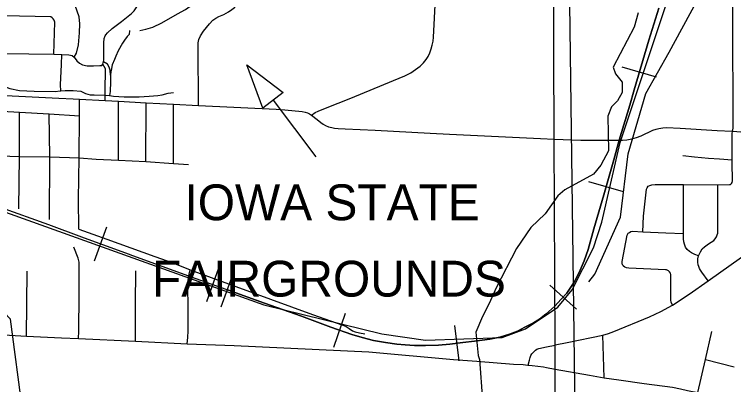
# Model space of a CAD drawing. Extents: x -1403959 to 81668, y -1400582 to 11018.
# Drawn here: x 7531.9 to 7677.6, y 8209.8 to 8284.8 of the extents above; entities that cross this region are included whole.
import ezdxf

# ---------------------------------------------------------------- set-up
doc = ezdxf.new("R2010")
doc.units = 0
for name, color, linetype in [('tdCiHydroTxt', 7, 'Continuous'), ('tdCiRRCL', 7, 'Continuous'), ('tdCiSectNmbr', 7, 'Continuous'), ('tdCiSectTwpRng', 7, 'Continuous'), ('tdCoSecRteBand', 7, 'Continuous'), ('tdCoStrucNonDivPri', 7, 'Continuous'), ('tdCoStrucSec', 7, 'Continuous'), ('tdCoSurfBitum', 7, 'Continuous'), ('tdCoTwpNameTxt', 7, 'Continuous')]:
    doc.layers.add(name, color=color, linetype=linetype)

msp = doc.modelspace()

# ---------------------------------------------------------------- linework, layer by layer
at = {"layer": 'tdCiHydroTxt'}
for points in [[(7543.99, 8276.06), (7544.47, 8276.9), (7544.82, 8278.62), (7545.03, 8281.03), (7545.09, 8282.84), (7544.99, 8284.25), (7543.79, 8287.74), (7543.55, 8288.67), (7543.47, 8290.45), (7543.41, 8293.01)], [(7550.41, 8280.6), (7550.72, 8281.01), (7551.69, 8281.91), (7553.53, 8283.33), (7555.58, 8284.91), (7556.14, 8285.47), (7556.55, 8286.06), (7557.03, 8286.89), (7557.23, 8287.69), (7557.19, 8288.74), (7557.08, 8289.79), (7556.63, 8290.51)], [(7557.27, 8281.51), (7558.46, 8281.77), (7559.88, 8282.19), (7561.71, 8283.04), (7564.93, 8284.9), (7566.52, 8285.73), (7567.44, 8286.41), (7567.79, 8286.87), (7568.18, 8287.61), (7568.25, 8288.58), (7568.19, 8290.36)], [(7569.13, 8266.32), (7569.06, 8278.31), (7569.09, 8278.99), (7569.24, 8279.66), (7569.56, 8280.38), (7570.18, 8281.37), (7571.36, 8282.86), (7572.03, 8283.57), (7572.64, 8284.02), (7573.26, 8284.34), (7574.29, 8284.75), (7575.24, 8285.25), (7575.89, 8285.73), (7576.44, 8286.14), (7577.07, 8286.79), (7577.61, 8287.4), (7577.99, 8288.06), (7578.27, 8288.8), (7578.29, 8289.24), (7578.25, 8289.86)], [(7539.71, 8283.88), (7539.53, 8284.07), (7539.24, 8284.23), (7529.69, 8284.43)], [(7539.88, 8276.7), (7540.03, 8283.21), (7539.93, 8283.6), (7539.71, 8283.88)], [(7555.17, 8281.51), (7555.09, 8280.71), (7554.72, 8280.26), (7554.14, 8279.51), (7553.75, 8278.94), (7552.9, 8277.36), (7552.41, 8276.26), (7552.11, 8275.6), (7551.64, 8274.52), (7551.45, 8273.41), (7551.42, 8273.16)], [(7549.9, 8275.12), (7549.96, 8275.54), (7549.96, 8278.96), (7550.04, 8279.88), (7550.26, 8280.42), (7550.41, 8280.6)], [(7529.71, 8276.85), (7539.88, 8276.7), (7541.47, 8276.62), (7542.89, 8276.59), (7543.57, 8276.44), (7543.99, 8276.06)], [(7541.24, 8269.26), (7541.23, 8270.47), (7541.37, 8274.61), (7541.47, 8276.62)], [(7543.99, 8276.06), (7544.54, 8275.37), (7545.08, 8274.88), (7545.67, 8274.51), (7546.57, 8274.34), (7547.91, 8274.34), (7549.16, 8274.37), (7549.6, 8274.4), (7549.81, 8274.66)], [(7549.81, 8274.66), (7549.87, 8274.93), (7549.9, 8275.12)], [(7551.36, 8272.46), (7551.23, 8273.45), (7551.06, 8274.09), (7550.72, 8274.66), (7549.9, 8275.12)], [(7550.22, 8267.28), (7550.23, 8268.38), (7550.25, 8269.82), (7550.34, 8273.15), (7550.29, 8273.72), (7549.81, 8274.66)], [(7551.42, 8273.16), (7551.36, 8272.46), (7551.32, 8271.08), (7551.23, 8269.14), (7551.11, 8268.31)], [(7529.59, 8270.08), (7529.61, 8270.08), (7530.06, 8270.1), (7530.94, 8269.73), (7532.92, 8269.31), (7535.85, 8269.21), (7540.09, 8269.12), (7541.16, 8269.25)], [(7541.16, 8269.25), (7541.24, 8269.26), (7542.16, 8269.37), (7543.75, 8269.34), (7545.34, 8269.17), (7546.26, 8268.71), (7547.21, 8268.46), (7547.99, 8268.46), (7550.19, 8268.38)], [(7550.19, 8268.38), (7550.23, 8268.38), (7551.11, 8268.31), (7551.97, 8268.17), (7554.09, 8268.07), (7557.14, 8268.05), (7559.16, 8268.17), (7560.9, 8268.31), (7561.8, 8268.46), (7563.04, 8268.78), (7564.07, 8268.93)]]:
    msp.add_lwpolyline(points, dxfattribs=at)
at = {"layer": 'tdCiRRCL'}
msp.add_lwpolyline([(7641.92, 8143.14), (7641.42, 8212.91), (7641.4, 8217.78), (7641.24, 8259.51), (7640.95, 8331.05)], dxfattribs=at)
msp.add_lwpolyline([(7641.92, 8143.14), (7641.42, 8212.91), (7641.4, 8217.78), (7641.24, 8259.51), (7640.95, 8331.05)], dxfattribs=at)
at = {"layer": 'tdCiSectNmbr'}
for points in [[(7592.05, 8264.37), (7592.8, 8264.86), (7593.41, 8265.17), (7594.89, 8265.73), (7600, 8267.8), (7608.67, 8271.38), (7610.93, 8272.3), (7612.21, 8272.94), (7613.13, 8273.58), (7614.06, 8274.29), (7614.77, 8274.95), (7615.26, 8275.63), (7615.66, 8276.22), (7616.05, 8276.95), (7616.3, 8277.78), (7616.53, 8278.54), (7616.69, 8279.32), (7616.78, 8280.14), (7618.07, 8304.79)], [(7530.05, 8268.32), (7540.86, 8267.75)], [(7540.86, 8267.75), (7543.78, 8267.62), (7545.06, 8267.55)], [(7545.06, 8267.55), (7550.22, 8267.28), (7552.94, 8267.18), (7558.55, 8266.86), (7564.11, 8266.57), (7569.13, 8266.32), (7584.89, 8265.58), (7586.65, 8265.43), (7590.14, 8265.11), (7590.78, 8264.98), (7591.27, 8264.8), (7591.63, 8264.63), (7592.05, 8264.37)], [(7592.05, 8264.37), (7593.17, 8263.46), (7593.94, 8262.84), (7594.42, 8262.52), (7594.9, 8262.26), (7595.52, 8262), (7596.15, 8261.84), (7596.73, 8261.74), (7597.44, 8261.67), (7598.84, 8261.56), (7604.97, 8261.3), (7616.11, 8260.68), (7619.98, 8260.5)], [(7619.98, 8260.5), (7638.44, 8259.64), (7641.24, 8259.51)], [(7658.82, 8260.15), (7661.21, 8261.27), (7661.85, 8261.51), (7662.42, 8261.64), (7663.2, 8261.77), (7664, 8261.83), (7666.77, 8261.7), (7674.27, 8261.25), (7677.29, 8261.1), (7677.37, 8261.1), (7677.46, 8261.09), (7683.65, 8260.56), (7689.52, 8260.18)], [(7641.24, 8259.51), (7646.62, 8259.26), (7649.6, 8259.25), (7654.07, 8259.25), (7655.07, 8259.25), (7655.96, 8259.34), (7656.93, 8259.53), (7657.88, 8259.79), (7658.82, 8260.15)], [(7668.57, 8228.07), (7672.43, 8230.76), (7689.63, 8243.01)], [(7641.42, 8217.79), (7643.83, 8218.29), (7651.07, 8219.8), (7652.25, 8220.14), (7653.33, 8220.53), (7660.52, 8223.51), (7662.81, 8224.56), (7665.19, 8225.84), (7668.57, 8228.07)], [(7525.09, 8220.11), (7525.09, 8220.11), (7534.34, 8219.54), (7541.4, 8219.23), (7544.87, 8219.11), (7556.37, 8218.54), (7566.88, 8218.01)], [(7651.34, 8211.12), (7651.07, 8219.8)], [(7566.88, 8218.01), (7576.4, 8217.66), (7603.7, 8216.4), (7620.82, 8214.84), (7625.57, 8214.48), (7632.98, 8213.93), (7634.95, 8213.81), (7635.89, 8213.72)], [(7635.92, 8213.72), (7636.21, 8214.72), (7636.37, 8215.28), (7636.51, 8215.65), (7636.71, 8215.99), (7637, 8216.36), (7637.42, 8216.73), (7637.72, 8216.91), (7638.1, 8217.06), (7639.69, 8217.42), (7641.4, 8217.78)], [(7641.4, 8217.78), (7641.42, 8217.79)], [(7635.89, 8213.72), (7635.92, 8213.72), (7636.75, 8213.64), (7637.88, 8213.51), (7639.06, 8213.34), (7639.68, 8213.23), (7641.42, 8212.91), (7641.43, 8212.91)], [(7641.43, 8212.91), (7648.39, 8211.64)], [(7648.39, 8211.64), (7651.34, 8211.12), (7654.32, 8210.7)], [(7654.32, 8210.7), (7659.47, 8209.97), (7665.18, 8209.21), (7666.83, 8208.89), (7668.23, 8208.57), (7670.31, 8208.13)]]:
    msp.add_lwpolyline(points, dxfattribs=at)
at = {"layer": 'tdCiSectTwpRng'}
for points in [[(7677.37, 8261.1), (7677.46, 8261.7), (7677.47, 8264.86), (7677.35, 8297.87)], [(7544.96, 8255.69), (7545.02, 8264.21), (7545.06, 8267.55)], [(7552.95, 8255.2), (7552.94, 8267.18)], [(7558.5, 8254.94), (7558.55, 8266.86)], [(7564.07, 8254.58), (7564.11, 8266.57)], [(7520.84, 8265.61), (7526.95, 8265.3), (7532.9, 8264.95), (7538.93, 8264.6), (7545.02, 8264.21)], [(7532.89, 8255.97), (7532.9, 8264.95)], [(7539.03, 8255.92), (7538.93, 8264.6)], [(7677.3, 8255.32), (7677.29, 8260.57), (7677.37, 8261.09)], [(7677.37, 8261.09), (7677.37, 8261.1), (7677.37, 8261.1)], [(7521.18, 8256.22), (7526.89, 8256.18), (7532.89, 8255.97), (7539.03, 8255.92), (7544.96, 8255.69), (7544.96, 8255.69)], [(7667.28, 8256.17), (7669.66, 8255.87), (7672.45, 8255.63), (7674.68, 8255.47), (7677.3, 8255.32)], [(7532.74, 8245.37), (7532.89, 8255.97)], [(7538.97, 8243.21), (7539.03, 8255.92)], [(7544.93, 8241.26), (7544.85, 8247.31), (7544.96, 8255.69)], [(7544.96, 8255.69), (7548.43, 8255.45), (7552.95, 8255.2), (7558.5, 8254.94), (7564.07, 8254.58), (7567.13, 8254.35)], [(7672.43, 8230.76), (7671.13, 8232.53), (7670.88, 8232.91), (7670.68, 8233.29), (7670.51, 8233.66), (7670.41, 8234.05), (7670.35, 8234.56), (7670.34, 8235.21), (7670.48, 8235.84), (7670.84, 8236.68), (7671.23, 8237.25), (7671.67, 8237.7), (7672.5, 8238.26), (7673.54, 8238.96), (7673.86, 8239.29), (7674.1, 8239.72), (7674.26, 8240.1), (7674.34, 8240.42), (7674.35, 8240.86), (7674.4, 8250.25), (7676.72, 8250.27), (7676.94, 8250.32), (7677.13, 8250.48), (7677.26, 8250.73), (7677.33, 8251.06), (7677.3, 8254.78), (7677.3, 8255.32)], [(7659.15, 8240.7), (7659.29, 8243.89), (7659.84, 8248.75), (7659.94, 8249.33), (7660.06, 8249.64), (7660.29, 8249.94), (7660.6, 8250.12), (7661.03, 8250.24), (7661.68, 8250.27), (7667.43, 8250.27), (7674.4, 8250.25)], [(7670.48, 8235.84), (7669.68, 8236.14), (7669.01, 8236.44), (7668.6, 8236.74), (7668.17, 8237.13), (7667.84, 8237.6), (7667.59, 8238.18), (7667.46, 8238.7), (7667.41, 8239.26), (7667.4, 8240.39), (7667.43, 8250.27)], [(7544.93, 8241.26), (7550.56, 8239.24)], [(7655.28, 8233.74), (7655.23, 8233.79), (7655.09, 8234.02), (7655, 8234.34), (7654.98, 8234.71), (7656.03, 8240.05), (7656.21, 8240.42), (7656.45, 8240.59), (7656.72, 8240.74), (7657.08, 8240.81), (7659.15, 8240.7), (7663.82, 8240.5)], [(7663.82, 8240.5), (7667.4, 8240.39)], [(7550.56, 8239.24), (7560.34, 8235.74), (7563.98, 8234.44), (7567.44, 8233.02), (7592.24, 8223.98), (7592.24, 8223.98)], [(7544.95, 8234.59), (7544.8, 8235.35), (7543.92, 8237.59)], [(7544.87, 8219.11), (7544.94, 8220.56), (7544.97, 8227.97), (7544.95, 8234.59)], [(7534.34, 8219.54), (7534.44, 8232.76)], [(7556.37, 8218.54), (7556.37, 8224.26), (7556.38, 8226.12), (7556.47, 8232.8)], [(7566.88, 8218.01), (7566.98, 8219.33), (7567.07, 8220.62), (7567.05, 8225.11), (7567.03, 8229.94), (7567.15, 8231.47), (7567.28, 8232.13), (7567.44, 8233.02)], [(7665.19, 8225.84), (7664.95, 8226.45), (7664.87, 8226.88), (7664.82, 8232.06), (7664.76, 8232.36), (7664.59, 8232.61), (7664.36, 8232.82), (7663.99, 8232.99), (7663.75, 8233.04), (7656.32, 8233.32), (7655.85, 8233.38), (7655.52, 8233.52), (7655.28, 8233.74)], [(7592.24, 8223.98), (7598.41, 8221.82), (7599.07, 8221.54), (7599.65, 8221.09), (7600.36, 8220.67), (7600.89, 8220.48), (7601.8, 8220.27), (7602.89, 8220.05)], [(7670.31, 8208.13), (7671.85, 8214.83), (7673.16, 8220.51)], [(7671.85, 8214.83), (7677.67, 8213.39)]]:
    msp.add_lwpolyline(points, dxfattribs=at)
at = {"layer": 'tdCoSecRteBand'}
for p, q in [((7661.96, 8272.03), (7655, 8274.07)), ((7655.25, 8248.83), (7648.27, 8250.81)), ((7548.12, 8234.86), (7550.57, 8241.69)), ((7570.84, 8226.6), (7573.3, 8233.43)), ((7573.78, 8225.54), (7576.24, 8232.37)), ((7645.74, 8225.06), (7640.33, 8229.9)), ((7596.58, 8217.35), (7598.95, 8224.21)), ((7621.99, 8214.55), (7621.1, 8221.74))]:
    msp.add_line(p, q, dxfattribs=at)
for points in [[(7501.68, 8253), (7525.64, 8246.21), (7582.4, 8225.9), (7606.28, 8220.05), (7615.18, 8218.76), (7630.67, 8219.28), (7635.44, 8221.08), (7641.96, 8225.42), (7644.87, 8228.93), (7649.17, 8237.46), (7650.86, 8242.65), (7654.57, 8258.82), (7664.88, 8289.64), (7673.02, 8304.73), (7684.51, 8321.19)], [(7648.25, 8230.6), (7649.46, 8232.12), (7654.68, 8243.71), (7656.24, 8256.53), (7659.79, 8268.73), (7664.54, 8277.12), (7670.07, 8287.33), (7675.6, 8301.52), (7680.98, 8311.73), (7688.18, 8321.02)], [(7662.39, 8285.99), (7660.39, 8279.55), (7657.43, 8269.49), (7656.57, 8266.38), (7654.4, 8259.25), (7653.31, 8255.29), (7651.31, 8248.21), (7649.25, 8241.32), (7648.09, 8237.16), (7647.28, 8234.82), (7646.26, 8232.47), (7645.25, 8230.54), (7643.75, 8228.28), (7642.66, 8227.07), (7641.33, 8225.62), (7639.54, 8224.05), (7638.22, 8223.01), (7637.03, 8222.25), (7635.28, 8221.36), (7633.79, 8220.57), (7632.16, 8219.97), (7630.24, 8219.38), (7628.16, 8218.95), (7625.07, 8218.58), (7622.73, 8218.29), (7620.07, 8217.96), (7617.79, 8217.78), (7615.12, 8217.68), (7612.92, 8217.68), (7611.04, 8217.81), (7609.34, 8217.94), (7607.06, 8218.27), (7604.6, 8218.72), (7602.29, 8219.28), (7600.19, 8219.94), (7596, 8221.39), (7590, 8223.59), (7582.52, 8226.25), (7575.01, 8228.96)], [(7575.01, 8228.96), (7582.52, 8226.25), (7590, 8223.59), (7596, 8221.39), (7600.19, 8219.94), (7602.29, 8219.28), (7604.6, 8218.72), (7607.06, 8218.27), (7609.34, 8217.94), (7611.04, 8217.81), (7612.92, 8217.68), (7615.12, 8217.68), (7617.79, 8217.78), (7620.07, 8217.96), (7622.73, 8218.29), (7625.07, 8218.58), (7628.16, 8218.95), (7630.24, 8219.38), (7632.16, 8219.97), (7633.79, 8220.57), (7635.28, 8221.36), (7637.03, 8222.25), (7638.22, 8223.01), (7639.54, 8224.05), (7641.33, 8225.62), (7642.66, 8227.07), (7643.75, 8228.28), (7645.25, 8230.54), (7646.26, 8232.47), (7647.28, 8234.82), (7648.09, 8237.16), (7649.25, 8241.32), (7651.31, 8248.21), (7653.31, 8255.29), (7654.4, 8259.25), (7656.57, 8266.38), (7657.43, 8269.49), (7660.39, 8279.55), (7662.39, 8285.99)], [(7528.89, 8245.68), (7538.78, 8242.18), (7545.47, 8239.67), (7554.93, 8236.27), (7555.82, 8235.94), (7568.65, 8231.25), (7574.73, 8229.06), (7575.01, 8228.96)], [(7528.89, 8245.68), (7538.78, 8242.18), (7545.47, 8239.67), (7554.93, 8236.27), (7555.82, 8235.94), (7568.65, 8231.25), (7574.73, 8229.06), (7575.01, 8228.96)]]:
    msp.add_lwpolyline(points, dxfattribs=at)
at = {"layer": 'tdCoStrucNonDivPri'}
msp.add_line((7593, 8255.9), (7584.38, 8267.39), dxfattribs=at)
msp.add_lwpolyline([(7582.19, 8265.77), (7578.95, 8274.51), (7586.34, 8268.93)], close=True, dxfattribs=at)
at = {"layer": 'tdCoSurfBitum'}
for points in [[(7658.2, 8285.08), (7657.43, 8282.18), (7653.15, 8274.09), (7653.61, 8272.71), (7654.98, 8271.03), (7654.98, 8268.9), (7654.06, 8267.22), (7652.84, 8266), (7652.08, 8264.17), (7652.23, 8257.14), (7650.7, 8254.24), (7649.17, 8252.41), (7643.37, 8249.21), (7641.99, 8247.99), (7639.39, 8244.33), (7636.49, 8241.58), (7633.59, 8237.31), (7629.46, 8229.37), (7628.08, 8226.16), (7626.71, 8223.57), (7625.33, 8220.36), (7625.79, 8215.63), (7626.09, 8214.87), (7626.7, 8206.62)], [(7656.46, 8153.01), (7655.54, 8152.86), (7654.62, 8153.16), (7653.4, 8154.99), (7649.59, 8156.98), (7604.53, 8157.78), (7598.12, 8158.39), (7594.15, 8160.07), (7592.01, 8161.6), (7583.92, 8169.24), (7549.27, 8197.66), (7535.67, 8201.18), (7533.54, 8204.09), (7531.1, 8223.02), (7528.36, 8225.77), (7524.54, 8228.83), (7519.96, 8233.72), (7515.38, 8239.68), (7510.19, 8247.77), (7508.51, 8249.6)]]:
    msp.add_lwpolyline(points, dxfattribs=at)
at = {"layer": 'tdCoTwpNameTxt'}
msp.add_lwpolyline([(7555.69, 8573.8), (7640.61, 8574.81), (7641.31, 8520.98), (7642.48, 8429.84), (7642.76, 8408.03), (7658.38, 8408.57), (7656.06, 8392.83), (7650.89, 8386.63), (7643.07, 8384.53), (7644.66, 8261.26), (7645.2, 8219.98), (7646.5, 8118.84), (7647.93, 8008.34), (7648.69, 7949.83)], dxfattribs=at)

# ---------------------------------------------------------------- texts
at = {"layer": 'tdCoStrucSec'}
for s, height, p in [('IOWA STATE', 7.255, (7566.31, 8243.06)), ('IOWA STATE', 7.255, (7566.31, 8243.06)), ('FAIRGROUNDS', 7.2546, (7559.75, 8227.59)), ('FAIRGROUNDS', 7.2546, (7559.75, 8227.59))]:
    msp.add_text(s, height=height, dxfattribs=at).set_placement(p)

doc.saveas('drawing.dxf')
